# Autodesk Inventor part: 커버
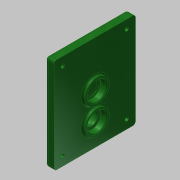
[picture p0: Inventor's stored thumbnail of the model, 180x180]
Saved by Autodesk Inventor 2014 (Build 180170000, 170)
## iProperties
Created: 2016-02
Part Number: 커버
Material: 일반
Document SubType Name: Modeling
Designer: mduedu
Density: 1 g/cm^3
Appearance: Smooth - Dark Forest Green
Mass: 100.463 g
Surface Area: 266.629 cm^2
Volume: 100.463 cm^3
Author: mduedu
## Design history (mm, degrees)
sketch "스케치1"
  geometry: L1 (63, 47)-(-47, 47); L2 (-47, 47)-(-47, -47); L3 (-47, -47)-(63, -47); L4 (63, -47)-(63, 47); 2 further points
  constraints: 8 end point, 2 parallel, 1 horizontal, 1 horizontal alignment, 1 midpoint, 1 perpendicular
  dimensions: "d102" = 94 distance of L3.end L1.start; "d104" = 47 distance from line of L2 point (0, 0); "d105" = 110 distance of L1.start L1.end
extrude "돌출1" new body sketch "스케치1" distance "d1" = 10; taper "d2" = 0 deg
sketch "스케치2"
  geometry: C1 r 14 at (0, 11); 1 further point
  constraints: 1 centre point, 1 vertical alignment
  dimensions: "d3" = 28 diameter of C1; "d6" = 11 distance of C1.centre point (0, 0)
extrude "돌출2" join sketch "스케치2" distance "d7" = 3; taper "d8" = 0 deg
sketch "스케치3"
  geometry: C1 r 14 at (0, -20); 1 further point
  constraints: 1 centre point, 1 vertical alignment
  dimensions: "d9" = 28 diameter of C1; "d10" = 20 distance of C1.centre point (0, 0)
extrude "돌출3" join sketch "스케치3" distance "d11" = 3; taper "d12" = 0 deg
hole "구멍1" diameter "d15" = 22; stored, may be unused: countersink angle "d19" = 90 deg, drill point angle "d21" = 0 deg; dims "d13" = 10, "d14" = 10, "d16" = 6, "d17" = 4, "d18" = 2, "d20" = 7
hole "구멍2" diameter "d24" = 18; stored, may be unused: countersink angle "d28" = 90 deg, drill point angle "d30" = 0 deg; dims "d22" = 10, "d23" = 10, "d25" = 6, "d26" = 4, "d27" = 2, "d29" = 1
hole "구멍3" diameter "d33" = 22; stored, may be unused: countersink angle "d37" = 90 deg, drill point angle "d39" = 0 deg; dims "d34" = 6, "d35" = 4, "d36" = 2, "d38" = 7, "d73" = 10, "d74" = 10
sketch "스케치4"
  geometry: C1 r 14 at (0, -20) reference; C2 r 18 at (0, -20); 1 further point
  constraints: 1 centre point, 1 coincident
  dimensions: "d40" = 36 diameter of C2
extrude "돌출4" join sketch "스케치4" distance "d41" = 4; taper "d42" = 0 deg
hole "구멍4" diameter "d45" = 22; stored, may be unused: countersink angle "d49" = 90 deg, drill point angle "d51" = 0 deg; dims "d43" = 10, "d44" = 10, "d46" = 6, "d47" = 4, "d48" = 2, "d50" = 7
hole "구멍5" diameter "d54" = 15; stored, may be unused: countersink angle "d58" = 90 deg, drill point angle "d60" = 0 deg; dims "d52" = 10, "d53" = 10, "d55" = 6, "d56" = 4, "d57" = 2, "d59" = 7
fillet "모깎기1" dims "d61" = 0.3
fillet "모깎기2" dims "d62" = 2
chamfer "모따기1" distance "d63" = 1; stored, may be unused: second distance "d64" = 2, angle "d65" = 45 deg
fillet "모깎기6" dims "d88" = 2
fillet "모깎기4" dims "d75" = 2
sketch "스케치9"
  geometry: L1 (47, 63)-(47, -47) reference; L2 (-47, 63)-(47, 63) reference; L3 (-47, -47)-(-47, 63) reference; L4 (47, -47)-(-47, -47) reference; L5 (37, 53)-(37, -37); L6 (37, -37)-(-37, -37); L7 (-37, -37)-(-37, 53); L8 (-37, 53)-(37, 53); C1 r 20 at (0, -20) reference; 5 further points
  constraints: 8 end point, 4 coincident, 3 other
  dimensions: "d107" = 10 distance between parallel lines of L8 L2
hole "구멍7" sketch "스케치9" at (-37, 53), (37, 53), (37, -37), (-37, -37) diameter "d108" = 4.5; stored, may be unused: countersink angle "d112" = 90 deg, drill point angle "d114" = 118 deg; dims "d109" = 6, "d110" = 8, "d111" = 4.6, "d113" = 8
fillet "모깎기8" dims "d106" = 3
fillet "모깎기9" dims "d115" = 3
node "솔리드1"
node "투영된 루프2"
